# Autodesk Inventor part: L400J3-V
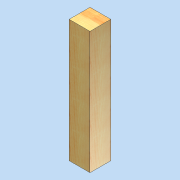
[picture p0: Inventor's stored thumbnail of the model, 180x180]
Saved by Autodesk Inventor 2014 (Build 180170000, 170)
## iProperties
Created: 2011-04
Part Number: L400J3-V
Document SubType Name: Modeling
Designer: david.appleford
Density: 0.540657 g/cm^3
Description: Lug Corner 0.5w 3 Slots
Cost Center: £6.00
Mass: 1000 g
Surface Area: 1180.48 cm^2
Volume: 1849.6 cm^3
Material: Generic
Appearance: Wood (Pine)
Justset: False
Author: david.appleford
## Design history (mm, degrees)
sketch "Sketch1"
  geometry: L1 (0, 0)-(68, 0); L2 (68, 0)-(68, 68); L3 (68, 68)-(0, 68); L4 (0, 68)-(0, 0)
  constraints: 8 end point, 2 parallel, 1 horizontal, 1 perpendicular
  dimensions: "d0" = 68 distance between parallel lines of L2 L4 (= t); "d1" = 68 distance between parallel lines of L1 L3 (= t)
extrude "Extrusion1" new body sketch "Sketch1" distance "d2" = 400; taper "d3" = 0 deg
body "Solid1"
other parameters: "t" = 68 [user parameter; used in 2 equation terms], "Cl" = 2 [user parameter]
